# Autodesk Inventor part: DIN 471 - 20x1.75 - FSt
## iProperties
Created: 2006-07
Material: FSt
Description: Sicherungsring
Vendor: Autodesk Inc.
Document SubType Name: Modeling
Standard: DIN 471
Designer: I.Baliuc
Standards Organization: DIN
Language: de-DE
Size Designation: 20 x 1.75
Categories: <MemberInstance Version="R10.0.0"><Categories><Category DisplayName="Wellenteile" InternalName="7f7aeb1f-a693-4053-b835-cee3144e0d98" Mnemonic="SHFT"><Category
Density: 7.85 g/cm^3
Mass: 2.79966 g
Surface Area: 6.94286 cm^2
Volume: 0.356644 cm^3
Abmessung: 20 x 1.75
Author: T.Messerschmitt
Comments: DIN 471 - 20 x 1.75
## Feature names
1. Körper [Extrusion]
